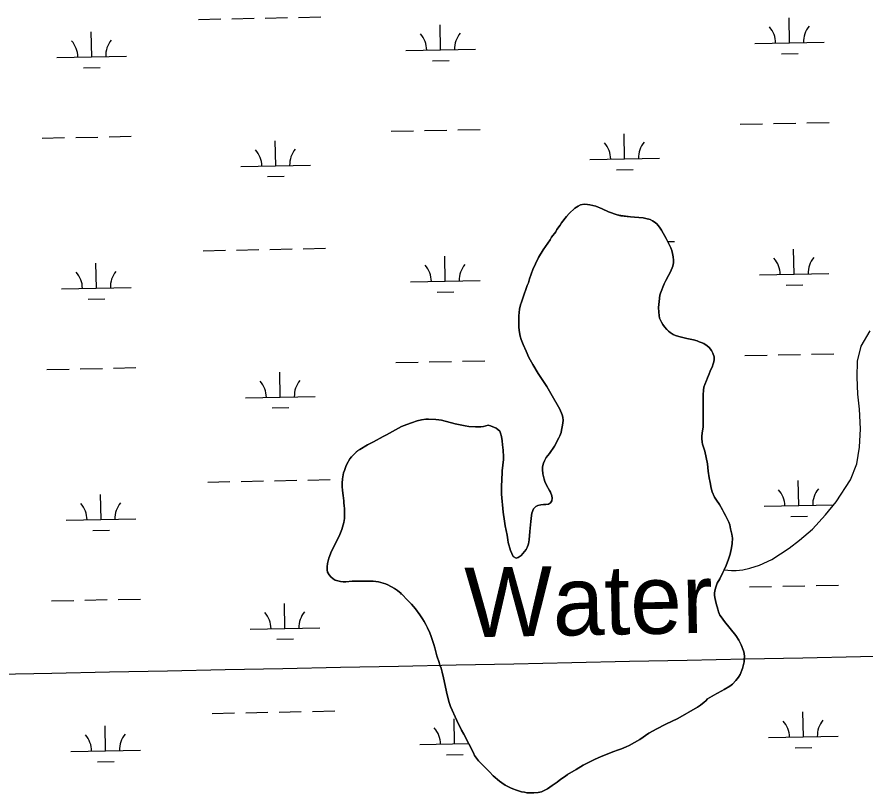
# Model space of a CAD drawing. Extents: x 3989314 to 4027622, y 243956 to 270014.
# Drawn here: x 4020534 to 4021754, y 255820 to 256937 of the extents above; entities that cross this region are included whole.
import ezdxf

# ---------------------------------------------------------------- set-up
doc = ezdxf.new("R2010")
doc.units = 0
for name, color, linetype in [('V-GRID-MAJR', 7, 'Continuous'), ('V-RIVR-IDEN', 7, 'Continuous'), ('V-TOPO-SHOR', 7, 'Continuous'), ('V-WETL-SWMP', 7, 'Continuous')]:
    doc.layers.add(name, color=color, linetype=linetype)

msp = doc.modelspace()

# ---------------------------------------------------------------- linework, layer by layer
at = {"layer": 'V-GRID-MAJR'}
msp.add_spline([(3993497.6, 255455.7), (3998815.3, 255559.8), (4004133, 255664.6), (4009450.7, 255770.2), (4014768.4, 255876.5), (4020086, 255983.7), (4025403.7, 256091.6)], degree=3, dxfattribs=at)
at = {"layer": 'V-TOPO-SHOR'}
for points in [[(4021255.5, 256160.1), (4021259.7, 256162.9), (4021266.6, 256171.4), (4021268.1, 256174.5), (4021270, 256179.5), (4021271.2, 256185.1), (4021272.1, 256197.1), (4021273.6, 256211.6), (4021274.3, 256220.5), (4021274.8, 256223.9), (4021277.2, 256229.7), (4021280.5, 256233.3), (4021283.7, 256234.7), (4021287.7, 256235.7), (4021291.7, 256236.1), (4021295.2, 256236.1), (4021298.9, 256236.5), (4021301.7, 256238.5), (4021303.5, 256241.3), (4021304.3, 256245), (4021303.8, 256248.4), (4021301.7, 256253.8), (4021300.1, 256256.4), (4021296.1, 256264.1), (4021293.8, 256269.3), (4021292.6, 256272.7), (4021290.7, 256280.4), (4021290.2, 256286.5), (4021290.5, 256290.2), (4021291.7, 256295.4), (4021293.1, 256299), (4021295.7, 256303.8), (4021300.2, 256309.5), (4021307.7, 256320.2), (4021313.8, 256331.8), (4021315.2, 256334.7), (4021316.9, 256339.6), (4021317.8, 256342.9), (4021319.2, 256350.4), (4021319.6, 256353.7), (4021319.8, 256357), (4021319.6, 256361.8), (4021318.7, 256364.9), (4021315, 256373.2), (4021313.1, 256376.7), (4021304.2, 256392.4), (4021296.3, 256405.6), (4021284, 256424.4), (4021276.2, 256437.2), (4021270.6, 256447.5), (4021266.9, 256456.4), (4021262.4, 256466.4), (4021259.7, 256473.6), (4021258.3, 256478.3), (4021257.3, 256483.2), (4021256.4, 256490.8), (4021256.1, 256496), (4021256.1, 256500.4), (4021256.4, 256507.6), (4021257.4, 256516.8), (4021258.8, 256523), (4021259.9, 256527), (4021262, 256532.6), (4021268.3, 256550.8), (4021270.1, 256555), (4021271.7, 256560.5), (4021276.6, 256574.1), (4021280.1, 256582.2), (4021284.7, 256591.5), (4021291.1, 256602.3), (4021301.1, 256616.5), (4021303.4, 256620.5), (4021309.4, 256628.4), (4021311.1, 256631.3), (4021315.8, 256637.9), (4021317.8, 256641), (4021324.9, 256650.2), (4021328.4, 256654.4), (4021336.7, 256662.2), (4021341.5, 256665.2), (4021345, 256667), (4021350.4, 256667.8), (4021355, 256667.7), (4021358.4, 256667.2), (4021366.9, 256664.9), (4021376.3, 256661.2), (4021385.2, 256656.8), (4021397.5, 256652.7), (4021402.7, 256651.4), (4021416.9, 256649.6), (4021422.6, 256649.3), (4021434.9, 256648.1), (4021439.1, 256647.5), (4021445.1, 256645.7), (4021448.3, 256644.2), (4021451.1, 256642.6), (4021454.6, 256639.5), (4021458.6, 256634.9), (4021461.4, 256630.8), (4021468, 256618.8), (4021474.8, 256605.1)], [(4021474.8, 256605.1), (4021476.2, 256601.1), (4021477.3, 256597.1), (4021478.4, 256592.2), (4021478.7, 256587.3), (4021478.7, 256583.7), (4021477.7, 256578.8), (4021474.4, 256570.7), (4021471.4, 256565.6), (4021467.7, 256558.3), (4021465.4, 256553.4), (4021460, 256540), (4021459.1, 256536.9), (4021457.9, 256528), (4021457.2, 256519.2), (4021457.5, 256512.5), (4021457.9, 256508), (4021458.7, 256504), (4021461.3, 256498.3), (4021463.2, 256494.9), (4021465.5, 256491.6), (4021468.9, 256487.7), (4021471.4, 256485.4), (4021474, 256483.4), (4021478.1, 256480.7), (4021481.4, 256479.3), (4021486.3, 256477.6), (4021497.9, 256474.7), (4021507.6, 256472.7), (4021512.5, 256471.3), (4021515.4, 256470.1), (4021518.3, 256469.2), (4021522.5, 256467.4), (4021527.1, 256464.3), (4021530.2, 256461.7), (4021533.4, 256457.5), (4021535.4, 256453.8), (4021537.1, 256448.5), (4021537.3, 256444.5), (4021536.8, 256441.4), (4021535.9, 256438.5), (4021534.1, 256433.7), (4021532.6, 256430.4), (4021529.2, 256421.8), (4021527.7, 256418.1), (4021526, 256414.6), (4021523.7, 256408.7), (4021522.5, 256404.7), (4021521.7, 256400.7), (4021521.4, 256394), (4021521.3, 256382.4), (4021521.3, 256351.3), (4021521.2, 256347.6), (4021519.8, 256338.6), (4021519.5, 256334.6), (4021519.5, 256330.9), (4021519.8, 256325.8), (4021520.6, 256322.7), (4021523.9, 256312.6), (4021525.7, 256303.7), (4021527.4, 256294.7), (4021528.5, 256284), (4021530.1, 256274.7), (4021531.6, 256267.7), (4021533, 256259.7), (4021534.4, 256254.3), (4021537.5, 256246.7), (4021540.3, 256242.3), (4021544.6, 256236.3), (4021549.3, 256228.3), (4021551.3, 256224.6), (4021553.3, 256220.3), (4021558.2, 256210.6), (4021559.5, 256206.8), (4021560.8, 256200.9), (4021561.5, 256197.3), (4021562.4, 256193.3), (4021563.3, 256187.6), (4021563.2, 256180.2), (4021562.1, 256174), (4021560, 256164.8), (4021557.9, 256157.5), (4021554.5, 256148.2), (4021551.6, 256142)], [(4021551.6, 256142), (4021562.2, 256141.2), (4021568.7, 256141.4), (4021578.2, 256142.2), (4021588.5, 256144.4), (4021602.4, 256148.7), (4021619.9, 256157.1), (4021645.1, 256173.3), (4021659.9, 256184.9), (4021678.4, 256200.5), (4021697.4, 256221.1), (4021712.5, 256239.9), (4021733.4, 256271.5), (4021742.5, 256294.4), (4021746.2, 256318.5), (4021747.4, 256345), (4021746.1, 256373.1), (4021743.7, 256394.9), (4021742.6, 256419.4), (4021743.5, 256442.2), (4021748.7, 256463.8), (4021761.3, 256485.8)], [(4021113.7, 256077.5), (4021107.4, 256086), (4021102, 256092.6), (4021097.3, 256097.8), (4021087, 256108.1), (4021081.5, 256112.6), (4021077.3, 256115.3), (4021067.6, 256120.8), (4021064.7, 256122.1), (4021057.6, 256124.2), (4021054.5, 256125), (4021046.5, 256126), (4021030.2, 256126), (4021022.7, 256126.1), (4021016.5, 256126), (4021007.4, 256124.9), (4021003.4, 256124.9), (4020999.6, 256125.5), (4020992.2, 256127.3), (4020989.1, 256129.3), (4020985.9, 256132.2), (4020983.4, 256134.8), (4020981.2, 256138.7), (4020980.6, 256142.1), (4020980.5, 256146.5), (4020981.2, 256151.5), (4020982, 256155), (4020983.2, 256159), (4020986.7, 256168.8), (4020997.6, 256190.6), (4021001.7, 256200.4), (4021004.5, 256210.3), (4021005.4, 256216), (4021005.4, 256230), (4021005.2, 256234.7), (4021004.7, 256238.1), (4021004.6, 256241.3), (4021003.8, 256249), (4021002.7, 256256.3), (4021002.1, 256262.1), (4021002.1, 256266.7), (4021002.5, 256273), (4021004.2, 256281.5), (4021005.3, 256285), (4021007.4, 256290.6), (4021008.9, 256294), (4021013.4, 256302), (4021015.7, 256304.9), (4021019.7, 256308.9), (4021022.3, 256311.4), (4021024.9, 256313.6), (4021027.5, 256315.4), (4021038.7, 256321.9), (4021043.5, 256324.5), (4021047.4, 256326.4), (4021060.9, 256333.8), (4021065.9, 256336.2), (4021087.6, 256348.1), (4021095.3, 256351.2), (4021102.1, 256353.7), (4021109.9, 256356.2), (4021116.2, 256357.7), (4021122.4, 256358.7), (4021126.2, 256358.8), (4021137, 256358.5), (4021141, 256357.9), (4021145, 256357.2), (4021164.7, 256352), (4021178.9, 256349.1), (4021184.4, 256348.2), (4021193.8, 256347.7), (4021201.6, 256347.9), (4021205.3, 256348.4), (4021209, 256349.1), (4021212.1, 256350.2), (4021215.3, 256349.1), (4021223.5, 256345.8), (4021226.1, 256344.2), (4021228.9, 256341.6), (4021230.1, 256338.7), (4021231.2, 256333.8), (4021232.3, 256327.8), (4021232.9, 256322.1), (4021233.5, 256314.1), (4021234, 256304.7), (4021234, 256301), (4021232.5, 256284.7), (4021231.8, 256269.6), (4021231.3, 256264.2), (4021231.4, 256251.2), (4021233.9, 256225.2), (4021235.4, 256212.4), (4021236.5, 256205.5), (4021239.3, 256192), (4021240.3, 256185.5), (4021241, 256181.6), (4021244.3, 256170), (4021246, 256165.7), (4021248.3, 256161.3), (4021252.5, 256159.2), (4021255.5, 256160.1)], [(4021551.6, 256142), (4021549.6, 256138.3), (4021545.1, 256129.2), (4021541.6, 256122.9), (4021539.6, 256117.5), (4021538.6, 256113.8), (4021537.8, 256108.9), (4021537.8, 256105.7), (4021538.1, 256102.4), (4021540, 256093.7), (4021542.3, 256085.5), (4021543.5, 256081.8), (4021545.4, 256077.2), (4021547.1, 256074.4), (4021551.9, 256068.1), (4021568.5, 256047.9), (4021572.7, 256041.3), (4021576.1, 256034.2), (4021579.5, 256025.7), (4021580.3, 256022.3), (4021580.9, 256017.3), (4021580.4, 256013.9), (4021580.1, 256010), (4021578.9, 256004.2), (4021577.8, 256000.2), (4021574.5, 255991.9), (4021572.2, 255987.7), (4021568.5, 255983.1), (4021563.6, 255978), (4021559.6, 255974.9), (4021551.4, 255970.1), (4021548.1, 255968.4), (4021540.8, 255964.4), (4021527.6, 255956.8), (4021525.3, 255954), (4021522.9, 255951.7), (4021517.7, 255947.5), (4021513.4, 255944.6), (4021484.8, 255928.4), (4021467.7, 255920.1), (4021453.6, 255912.9), (4021449.6, 255910.8), (4021443.4, 255907.2), (4021430.1, 255898.1), (4021414.8, 255889.8), (4021410.5, 255887.6), (4021403.9, 255884.9), (4021399.5, 255883.5), (4021391.2, 255880.5), (4021385.6, 255878.2), (4021374.6, 255874), (4021365.2, 255869.7), (4021348.9, 255861.1), (4021338.9, 255855.3), (4021326.4, 255847.8), (4021323.5, 255845.5), (4021316.5, 255841), (4021311.2, 255836.8), (4021307.1, 255834), (4021304.2, 255832.3), (4021297.3, 255827.3), (4021293.4, 255825.2), (4021288.6, 255823.1), (4021284.2, 255822.2), (4021278, 255821.4), (4021271.1, 255821.7), (4021267.7, 255821.7), (4021264.5, 255822.4), (4021259.9, 255823.2), (4021252.8, 255825.5), (4021247.6, 255827.5), (4021244.2, 255828.8), (4021236.8, 255832.5), (4021231.7, 255835.7), (4021228.3, 255838.4), (4021219.5, 255846), (4021214.1, 255851.6), (4021198.1, 255867.4), (4021192.5, 255875.4), (4021190.8, 255879.1), (4021177.1, 255906.1), (4021174, 255911.5), (4021166.9, 255925.6), (4021158.1, 255945.6), (4021156.1, 255951.2), (4021153, 255962.5), (4021148, 255986.7), (4021146.1, 255995), (4021144.3, 256000.8), (4021142.7, 256005), (4021141.7, 256008.8), (4021138.4, 256018.7), (4021135.6, 256029.9), (4021134.2, 256034.7), (4021130.2, 256046.2), (4021128, 256051.6), (4021124.8, 256058.9), (4021122.6, 256063.4), (4021120.2, 256068), (4021117.7, 256071.9), (4021113.7, 256077.5)]]:
    msp.add_lwpolyline(points, dxfattribs=at)
at = {"layer": 'V-WETL-SWMP'}
for p, q in [((4020843.5, 256934.6), (4020875.5, 256935.2)), ((4020891.5, 256935.5), (4020923.5, 256936.2)), ((4020939.5, 256936.5), (4020971.5, 256937.1)), ((4021645.6, 256899.8), (4021644.9, 256935.8)), ((4020795.6, 256933.6), (4020827.5, 256934.2)), ((4021143.8, 256889.8), (4021143.1, 256925.8)), ((4020642, 256879.8), (4020641.3, 256915.8)), ((4021595.6, 256898.8), (4021695.6, 256900.8)), ((4021093.8, 256888.8), (4021193.8, 256890.8)), ((4020592, 256878.8), (4020692, 256880.8)), ((4021132.1, 256874.1), (4021156.1, 256874.6)), ((4021633.9, 256884.1), (4021657.9, 256884.6)), ((4020630.3, 256864.1), (4020654.3, 256864.6)), ((4021574.5, 256782.9), (4021606.5, 256783.6)), ((4021622.5, 256783.9), (4021654.5, 256784.5)), ((4021670.5, 256784.8), (4021702.5, 256785.5)), ((4020618.9, 256763.9), (4020650.9, 256764.5)), ((4020666.9, 256764.8), (4020698.9, 256765.5)), ((4021072.7, 256772.9), (4021104.7, 256773.6)), ((4021120.7, 256773.9), (4021152.7, 256774.5)), ((4021168.7, 256774.8), (4021200.7, 256775.5)), ((4021408.4, 256733.2), (4021407.7, 256769.2)), ((4020570.9, 256762.9), (4020602.9, 256763.6)), ((4020906.6, 256723.2), (4020905.9, 256759.2)), ((4021358.4, 256732.2), (4021458.4, 256734.2)), ((4020856.6, 256722.2), (4020956.6, 256724.2)), ((4021396.7, 256717.5), (4021420.7, 256718)), ((4020894.9, 256707.5), (4020918.9, 256708)), ((4021470.3, 256614.3), (4021480, 256614.5)), ((4020802.2, 256601), (4020834.2, 256601.6)), ((4020850.2, 256601.9), (4020882.2, 256602.6)), ((4020898.2, 256602.9), (4020930.2, 256603.5)), ((4020946.2, 256603.9), (4020978.1, 256604.5)), ((4021652.3, 256567.2), (4021651.5, 256603.2)), ((4020648.6, 256547.2), (4020647.9, 256583.2)), ((4021150.4, 256557.2), (4021149.7, 256593.2)), ((4021100.5, 256556.2), (4021200.4, 256558.2)), ((4021602.3, 256566.2), (4021702.2, 256568.2)), ((4020598.6, 256546.2), (4020698.6, 256548.2)), ((4021640.6, 256551.5), (4021664.6, 256552)), ((4021138.8, 256541.5), (4021162.7, 256542)), ((4020636.9, 256531.5), (4020660.9, 256532)), ((4021581.2, 256450.3), (4021613.2, 256450.9)), ((4021629.1, 256451.3), (4021661.1, 256451.9)), ((4021677.1, 256452.2), (4021709.1, 256452.9)), ((4021079.3, 256440.3), (4021111.3, 256440.9)), ((4021127.3, 256441.3), (4021159.3, 256441.9)), ((4021175.3, 256442.2), (4021207.3, 256442.9)), ((4020577.5, 256430.3), (4020609.5, 256430.9)), ((4020625.5, 256431.3), (4020657.5, 256431.9)), ((4020673.5, 256432.2), (4020705.5, 256432.9)), ((4020913.2, 256390.6), (4020912.5, 256426.6)), ((4020863.3, 256389.6), (4020963.2, 256391.6)), ((4020901.6, 256374.9), (4020925.5, 256375.4)), ((4020808.8, 256268.4), (4020840.8, 256269)), ((4020856.8, 256269.3), (4020888.8, 256270)), ((4020904.8, 256270.3), (4020936.8, 256270.9)), ((4020952.8, 256271.3), (4020984.8, 256271.9)), ((4021658.9, 256234.6), (4021658.2, 256270.6)), ((4020655.3, 256214.6), (4020654.5, 256250.6)), ((4021608.9, 256233.6), (4021708.9, 256235.6)), ((4020605.3, 256213.6), (4020705.3, 256215.6)), ((4021647.2, 256218.9), (4021671.2, 256219.4)), ((4020643.6, 256198.9), (4020667.6, 256199.4)), ((4021587.8, 256117.7), (4021619.8, 256118.3)), ((4021635.8, 256118.7), (4021667.8, 256119.3)), ((4021683.8, 256119.6), (4021715.8, 256120.3)), ((4021086, 256107.7), (4021087.4, 256107.7)), ((4020584.2, 256097.7), (4020616.2, 256098.3)), ((4020632.2, 256098.7), (4020664.2, 256099.3)), ((4020680.2, 256099.6), (4020712.1, 256100.2)), ((4020919.9, 256057.9), (4020919.2, 256093.9)), ((4020869.9, 256057), (4020969.9, 256058.9)), ((4020908.2, 256042.3), (4020932.2, 256042.8)), ((4020815.4, 255935.8), (4020847.4, 255936.4)), ((4020863.4, 255936.7), (4020895.4, 255937.4)), ((4020911.4, 255937.7), (4020943.4, 255938.3)), ((4020959.4, 255938.6), (4020991.4, 255939.3)), ((4021665.5, 255902), (4021664.8, 255938)), ((4021163.7, 255892), (4021163, 255928)), ((4020661.9, 255882), (4020661.2, 255918)), ((4021615.5, 255901), (4021715.5, 255903)), ((4021113.7, 255891), (4021184.1, 255892.4)), ((4021653.8, 255886.3), (4021677.8, 255886.8)), ((4020611.9, 255881), (4020711.9, 255883)), ((4021152, 255876.3), (4021176, 255876.8)), ((4020650.2, 255866.3), (4020674.2, 255866.8))]:
    msp.add_line(p, q, dxfattribs=at)
for points in [[(4021358.4, 256667.2), (4021355, 256667.7), (4021350.4, 256667.8), (4021345, 256667), (4021341.5, 256665.2), (4021336.7, 256662.2), (4021328.4, 256654.4), (4021324.9, 256650.2), (4021317.8, 256641), (4021315.8, 256637.9), (4021311.1, 256631.3), (4021309.4, 256628.4), (4021303.4, 256620.5), (4021301.1, 256616.5), (4021291.1, 256602.3), (4021284.7, 256591.5), (4021280.1, 256582.2), (4021276.6, 256574.1), (4021271.7, 256560.5), (4021270.1, 256555), (4021268.3, 256550.8), (4021262, 256532.6), (4021259.9, 256527), (4021258.8, 256523), (4021257.4, 256516.8), (4021256.4, 256507.6), (4021256.1, 256500.4), (4021256.1, 256496), (4021256.4, 256490.8), (4021257.3, 256483.2), (4021258.3, 256478.3), (4021259.7, 256473.6), (4021262.4, 256466.4), (4021266.9, 256456.4), (4021270.6, 256447.5), (4021276.2, 256437.2), (4021284, 256424.4), (4021296.3, 256405.6), (4021304.2, 256392.4), (4021313.1, 256376.7), (4021315, 256373.2), (4021318.7, 256364.9), (4021319.6, 256361.8), (4021319.8, 256357), (4021319.6, 256353.7), (4021319.2, 256350.4), (4021317.8, 256342.9), (4021316.9, 256339.6), (4021315.2, 256334.7), (4021313.8, 256331.8), (4021307.7, 256320.2), (4021300.2, 256309.5), (4021295.7, 256303.8), (4021293.1, 256299), (4021291.7, 256295.4), (4021290.5, 256290.2), (4021290.2, 256286.5), (4021290.7, 256280.4), (4021292.6, 256272.7), (4021293.8, 256269.3), (4021296.1, 256264.1), (4021300.1, 256256.4), (4021301.7, 256253.8), (4021303.8, 256248.4), (4021304.3, 256245), (4021303.5, 256241.3), (4021301.7, 256238.5), (4021298.9, 256236.5), (4021295.2, 256236.1), (4021291.7, 256236.1), (4021287.7, 256235.7), (4021283.7, 256234.7), (4021280.5, 256233.3), (4021277.2, 256229.7), (4021274.8, 256223.9), (4021274.3, 256220.5), (4021273.6, 256211.6), (4021272.1, 256197.1), (4021271.2, 256185.1), (4021270, 256179.5), (4021268.1, 256174.5), (4021266.6, 256171.4), (4021259.7, 256162.9), (4021255.5, 256160.1)], [(4021551.6, 256142), (4021554.5, 256148.2), (4021557.9, 256157.5), (4021560, 256164.8), (4021562.1, 256174), (4021563.2, 256180.2), (4021563.3, 256187.6), (4021562.4, 256193.3), (4021561.5, 256197.3), (4021560.8, 256200.9), (4021559.5, 256206.8), (4021558.2, 256210.6), (4021553.3, 256220.3), (4021551.3, 256224.6), (4021549.3, 256228.3), (4021544.6, 256236.3), (4021540.3, 256242.3), (4021537.5, 256246.7), (4021534.4, 256254.3), (4021533, 256259.7), (4021531.6, 256267.7), (4021530.1, 256274.7), (4021528.5, 256284), (4021527.4, 256294.7), (4021525.7, 256303.7), (4021523.9, 256312.6), (4021520.6, 256322.7), (4021519.8, 256325.8), (4021519.5, 256330.9), (4021519.5, 256334.6), (4021519.8, 256338.6), (4021521.2, 256347.6), (4021521.3, 256351.3), (4021521.3, 256382.4), (4021521.4, 256394), (4021521.7, 256400.7), (4021522.5, 256404.7), (4021523.7, 256408.7), (4021526, 256414.6), (4021527.7, 256418.1), (4021529.2, 256421.8), (4021532.6, 256430.4), (4021534.1, 256433.7), (4021535.9, 256438.5), (4021536.8, 256441.4), (4021537.3, 256444.5), (4021537.1, 256448.5), (4021535.4, 256453.8), (4021533.4, 256457.5), (4021530.2, 256461.7), (4021527.1, 256464.3), (4021522.5, 256467.4), (4021518.3, 256469.2), (4021515.4, 256470.1), (4021512.5, 256471.3), (4021507.6, 256472.7), (4021497.9, 256474.7), (4021486.3, 256477.6), (4021481.4, 256479.3), (4021478.1, 256480.7), (4021474, 256483.4), (4021471.4, 256485.4), (4021468.9, 256487.7), (4021465.5, 256491.6), (4021463.2, 256494.9), (4021461.3, 256498.3), (4021458.7, 256504), (4021457.9, 256508), (4021457.5, 256512.5), (4021457.2, 256519.2), (4021457.9, 256528), (4021459.1, 256536.9), (4021460, 256540), (4021465.4, 256553.4), (4021467.7, 256558.3), (4021471.4, 256565.6), (4021474.4, 256570.7), (4021477.7, 256578.8), (4021478.7, 256583.7), (4021478.7, 256587.3), (4021478.4, 256592.2), (4021477.3, 256597.1), (4021476.2, 256601.1), (4021474.8, 256605.1), (4021468, 256618.8), (4021461.4, 256630.8), (4021458.6, 256634.9), (4021454.6, 256639.5), (4021451.1, 256642.6), (4021448.3, 256644.2), (4021445.1, 256645.7), (4021439.1, 256647.5), (4021434.9, 256648.1), (4021422.6, 256649.3), (4021416.9, 256649.6), (4021402.7, 256651.5), (4021397.5, 256652.7), (4021385.2, 256656.8), (4021376.3, 256661.2), (4021366.9, 256664.9), (4021358.4, 256667.2)], [(4021255.5, 256160.1), (4021252.5, 256159.2), (4021248.3, 256161.3), (4021246, 256165.7), (4021244.3, 256170), (4021241, 256181.6), (4021240.3, 256185.5), (4021239.3, 256191.9), (4021236.5, 256205.5), (4021235.4, 256212.4), (4021233.9, 256225.2), (4021231.4, 256251.2), (4021231.3, 256264.2), (4021231.8, 256269.6), (4021232.5, 256284.7), (4021234, 256301), (4021234, 256304.7), (4021233.5, 256314.1), (4021232.9, 256322.1), (4021232.3, 256327.8), (4021231.2, 256333.8), (4021230.1, 256338.7), (4021228.9, 256341.6), (4021226.1, 256344.2), (4021223.5, 256345.8), (4021215.3, 256349.1), (4021212.1, 256350.2), (4021209, 256349.1), (4021205.3, 256348.4), (4021201.6, 256347.9), (4021193.8, 256347.7), (4021184.4, 256348.2), (4021178.9, 256349.1), (4021164.7, 256352), (4021145, 256357.2), (4021141, 256357.9), (4021137, 256358.5), (4021126.2, 256358.8), (4021122.4, 256358.7), (4021116.2, 256357.7), (4021109.9, 256356.2), (4021102.1, 256353.7), (4021095.3, 256351.2), (4021087.6, 256348.1), (4021065.9, 256336.2), (4021060.9, 256333.8), (4021047.4, 256326.4), (4021043.5, 256324.5), (4021038.7, 256321.9), (4021027.5, 256315.4), (4021024.9, 256313.5), (4021022.3, 256311.4), (4021019.7, 256308.9), (4021015.7, 256304.9), (4021013.4, 256302), (4021008.9, 256294), (4021007.4, 256290.6), (4021005.3, 256285), (4021004.2, 256281.5), (4021002.5, 256273), (4021002.1, 256266.7), (4021002.1, 256262.1), (4021002.7, 256256.3), (4021003.8, 256249), (4021004.6, 256241.3), (4021004.7, 256238.1), (4021005.2, 256234.7), (4021005.4, 256230), (4021005.4, 256216), (4021004.5, 256210.3), (4021001.7, 256200.4), (4020997.6, 256190.6), (4020986.7, 256168.8), (4020983.2, 256159), (4020982, 256155), (4020981.2, 256151.5), (4020980.5, 256146.5), (4020980.6, 256142.1), (4020981.2, 256138.7), (4020983.4, 256134.8), (4020985.9, 256132.2), (4020989.1, 256129.3), (4020992.2, 256127.3), (4020999.6, 256125.5), (4021003.4, 256124.9), (4021007.4, 256124.9), (4021016.5, 256126), (4021022.7, 256126.1), (4021030.2, 256126), (4021046.5, 256126), (4021054.5, 256125), (4021057.6, 256124.2), (4021064.7, 256122.1), (4021067.6, 256120.8), (4021077.3, 256115.3), (4021081.5, 256112.6), (4021087, 256108.1), (4021097.3, 256097.8), (4021102, 256092.6), (4021107.4, 256086), (4021113.7, 256077.5)], [(4021113.7, 256077.5), (4021117.7, 256071.9), (4021120.2, 256068), (4021122.6, 256063.4), (4021124.8, 256058.9), (4021128, 256051.6), (4021130.2, 256046.2), (4021134.2, 256034.7), (4021135.6, 256029.9), (4021138.4, 256018.7), (4021141.7, 256008.8), (4021142.7, 256005), (4021144.3, 256000.8), (4021146.1, 255995), (4021148, 255986.7), (4021153, 255962.5), (4021156.1, 255951.2), (4021158.1, 255945.6), (4021166.9, 255925.6), (4021174, 255911.5), (4021177.1, 255906.1), (4021190.8, 255879.1), (4021192.5, 255875.4), (4021198.1, 255867.4), (4021214.1, 255851.6), (4021219.5, 255846), (4021228.3, 255838.4), (4021231.7, 255835.7), (4021236.8, 255832.5), (4021244.2, 255828.8), (4021247.6, 255827.5), (4021252.8, 255825.5), (4021259.9, 255823.2), (4021264.5, 255822.4), (4021267.7, 255821.7), (4021271.1, 255821.7), (4021278, 255821.4), (4021284.2, 255822.2), (4021288.6, 255823.1), (4021293.4, 255825.2), (4021297.3, 255827.3), (4021304.2, 255832.3), (4021307.1, 255834), (4021311.2, 255836.8), (4021316.5, 255841), (4021323.5, 255845.5), (4021326.4, 255847.8), (4021338.9, 255855.3), (4021348.9, 255861.1), (4021365.2, 255869.7), (4021374.6, 255874), (4021385.6, 255878.2), (4021391.2, 255880.5), (4021399.5, 255883.5), (4021403.9, 255884.9), (4021410.5, 255887.6), (4021414.8, 255889.8), (4021430.1, 255898.1), (4021443.4, 255907.2), (4021449.6, 255910.8), (4021453.6, 255912.9), (4021467.7, 255920.1), (4021484.8, 255928.4), (4021513.4, 255944.6), (4021517.7, 255947.5), (4021522.9, 255951.7), (4021525.3, 255954), (4021527.6, 255956.8), (4021540.8, 255964.4), (4021548.1, 255968.4), (4021551.4, 255970.1), (4021559.6, 255974.9), (4021563.6, 255978), (4021568.5, 255983.1), (4021572.2, 255987.7), (4021574.5, 255991.9), (4021577.8, 256000.2), (4021578.9, 256004.2), (4021580.1, 256010), (4021580.4, 256013.9), (4021580.9, 256017.3), (4021580.3, 256022.3), (4021579.5, 256025.7), (4021576.1, 256034.2), (4021572.7, 256041.3), (4021568.5, 256047.9), (4021551.9, 256068.1), (4021547.1, 256074.4), (4021545.4, 256077.2), (4021543.5, 256081.8), (4021542.3, 256085.5), (4021540, 256093.7), (4021538.1, 256102.4), (4021537.8, 256105.7), (4021537.8, 256108.9), (4021538.6, 256113.8), (4021539.6, 256117.5), (4021541.6, 256122.9), (4021545.1, 256129.2), (4021549.6, 256138.3), (4021551.6, 256142)]]:
    msp.add_lwpolyline(points, dxfattribs=at)
for centre, start, end in [((4021590.4, 256899.2), 0.3699, 41.9135), ((4021700.8, 256901.4), 140.3699, 181.9135), ((4021088.6, 256889.2), 0.3699, 41.9135), ((4021199, 256891.4), 140.3699, 181.9135), ((4020586.8, 256879.2), 0.3699, 41.9135), ((4020697.2, 256881.4), 140.3699, 181.9135), ((4021353.2, 256732.5), 0.3699, 41.9135), ((4021463.6, 256734.7), 140.3699, 181.9135), ((4020851.4, 256722.5), 0.3699, 41.9135), ((4020961.8, 256724.7), 140.3699, 181.9135), ((4021205.7, 256558.8), 140.3699, 181.9135), ((4021597, 256566.6), 0.3699, 41.9135), ((4021707.5, 256568.8), 140.3699, 181.9135), ((4020593.4, 256546.6), 0.3699, 41.9135), ((4020703.9, 256548.8), 140.3699, 181.9135), ((4021095.2, 256556.6), 0.3699, 41.9135), ((4020858, 256389.9), 0.3699, 41.9135), ((4020968.5, 256392.1), 140.3699, 181.9135), ((4021603.6, 256233.9), 0.3699, 41.9135), ((4021714.1, 256236.1), 140.3699, 181.9135), ((4020600, 256213.9), 0.3699, 41.9135), ((4020710.5, 256216.1), 140.3699, 181.9135), ((4020975.1, 256059.5), 140.3699, 181.9135), ((4020864.6, 256057.3), 0.3699, 41.9135), ((4021610.3, 255901.3), 0.3699, 41.9135), ((4021720.7, 255903.5), 140.3699, 181.9135), ((4021108.5, 255891.3), 0.3699, 41.9135), ((4020606.6, 255881.3), 0.3699, 41.9135), ((4020717.1, 255883.5), 140.3699, 181.9135), ((4021218.9, 255893.5), 180.6375, 181.9135)]:
    msp.add_arc(centre, 35.2, start, end, dxfattribs=at)

# ---------------------------------------------------------------- texts
at = {"layer": 'V-RIVR-IDEN'}
msp.add_text('Water', height=100, rotation=1.0724, dxfattribs=at).set_placement((4021179.4, 256045.1))

doc.saveas('drawing.dxf')
